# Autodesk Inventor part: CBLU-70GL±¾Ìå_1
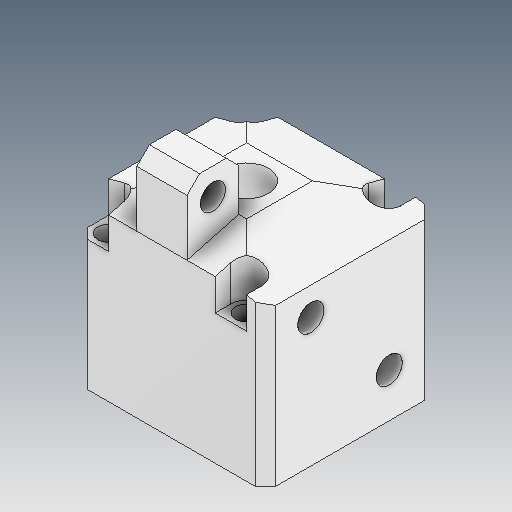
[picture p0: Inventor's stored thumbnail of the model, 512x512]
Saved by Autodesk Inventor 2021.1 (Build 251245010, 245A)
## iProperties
Created: 2021-05
Part Number: CBLU-70GL±¾Ìå_1
Material: Ogólny
Document SubType Name: Modeling
Designer: user
Density: 1 g/cm^3
Appearance: Domyślna
Author: user
Revision Number: ÈÎºÎ
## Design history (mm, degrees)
feature "ÊäÈë1"
feature "ÊäÈë2"
node "Bryła1"
node "Bryła2"
